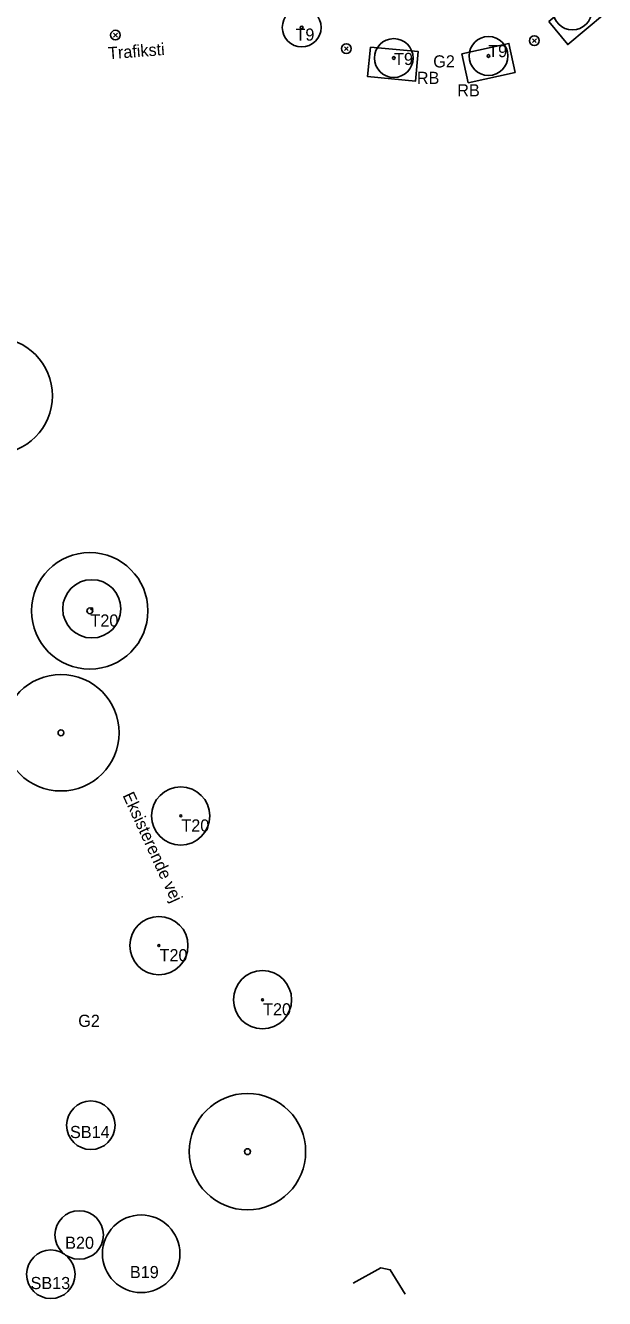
# Model space of a CAD drawing. Extents: x 0 to 512122, y 0 to 6212554.
# Drawn here: x 511804.4 to 511864.2, y 6211694 to 6211825.1 of the extents above; entities that cross this region are included whole.
import ezdxf

# ---------------------------------------------------------------- set-up
doc = ezdxf.new("R2010")
doc.units = 0
for name, color, linetype in [('_eks bevares træer', 7, 'Continuous'), ('_Fjernes træer', 7, 'Continuous'), ('_lights', 7, 'Continuous'), ('_ny træer T20', 7, 'Continuous'), ('_Rodvenligtbærelag', 7, 'Continuous'), ('L40 jord udlagt muld og grøft', 7, 'Continuous'), ('Skel', 7, 'Continuous'), ('TV_U_AFM_Symbl_Gul', 7, 'Continuous'), ('TV_U_LYS_Mastenummer', 7, 'Continuous')]:
    doc.layers.add(name, color=color, linetype=linetype)

# ---------------------------------------------------------------- blocks, each defined once
blk = doc.blocks.new('SOLITAIRE TREES')
at = {"layer": 'Skel'}
for radius in [2, 0.141]:
    blk.add_circle((0, 0), radius, dxfattribs=at)

msp = doc.modelspace()

# ---------------------------------------------------------------- linework, layer by layer
at = {"layer": '_eks bevares træer'}
for centre, radius in [((511808.08, 6211752.27), 6), ((511808.08, 6211752.27), 6), ((511808.08, 6211752.27), 0.3), ((511827.32, 6211709.11), 6), ((511827.32, 6211709.11), 6), ((511827.32, 6211709.11), 0.3)]:
    msp.add_circle(centre, radius, dxfattribs=at)
at = {"layer": '_Fjernes træer'}
for centre, radius in [((511801.2, 6211786.99), 6), ((511811.05, 6211764.83), 6), ((511811.05, 6211764.83), 0.3)]:
    msp.add_circle(centre, radius, dxfattribs=at)
at = {"layer": '_lights'}
for p, q in [((511813.9, 6211824.35), (511813.51, 6211823.95)), ((511813.51, 6211824.34), (511813.9, 6211823.95)), ((511837.32, 6211822.95), (511837.72, 6211822.56)), ((511837.72, 6211822.96), (511837.33, 6211822.56)), ((511857.12, 6211823.78), (511856.72, 6211823.39)), ((511856.72, 6211823.78), (511857.11, 6211823.38))]:
    msp.add_line(p, q, dxfattribs=at)
for centre, start, end in [((511813.7, 6211824.15), 315.5636, 315), ((511813.7, 6211824.15), 315, 315.5636), ((511837.52, 6211822.76), 315.5636, 315), ((511856.91, 6211823.58), 315.5636, 315), ((511856.91, 6211823.58), 315, 315.5636), ((511837.52, 6211822.76), 315, 315.5636)]:
    msp.add_arc(centre, 0.5, start, end, dxfattribs=at)
at = {"layer": '_ny træer T20'}
for centre, radius in [((511811.26, 6211765.04), 3), ((511811.26, 6211765.04), 3), ((511811.26, 6211765.04), 0.1), ((511820.43, 6211743.7), 3), ((511820.43, 6211743.7), 3), ((511820.43, 6211743.7), 0.1), ((511818.18, 6211730.34), 3), ((511818.18, 6211730.34), 3), ((511818.18, 6211730.34), 0.1), ((511828.87, 6211724.76), 3), ((511828.87, 6211724.76), 3), ((511828.87, 6211724.76), 0.1)]:
    msp.add_circle(centre, radius, dxfattribs=at)
at = {"layer": '_Rodvenligtbærelag'}
for points in [[(511858.39, 6211825.54), (511862.2, 6211828.71), (511864.16, 6211826.35), (511860.35, 6211823.18)], [(511840, 6211822.92), (511844.93, 6211822.45), (511844.64, 6211819.4), (511839.71, 6211819.88)], [(511849.44, 6211822.23), (511854.28, 6211823.29), (511854.93, 6211820.3), (511850.09, 6211819.24)]]:
    msp.add_lwpolyline(points, close=True, dxfattribs=at)
at = {"layer": 'L40 jord udlagt muld og grøft'}
msp.add_lwpolyline([(511838.21, 6211695.57), (511841.07, 6211697.15), (511842.04, 6211696.95), (511843.58, 6211694.44)], dxfattribs=at)
at = {"layer": 'TV_U_LYS_Mastenummer'}
for centre, radius in [((511811.16, 6211711.83), 2.5), ((511811.16, 6211711.83), 2.5), ((511809.96, 6211700.53), 2.5), ((511809.96, 6211700.53), 2.5), ((511816.35, 6211698.59), 4), ((511816.35, 6211698.59), 4), ((511807.03, 6211696.48), 2.5), ((511807.03, 6211696.48), 2.5)]:
    msp.add_circle(centre, radius, dxfattribs=at)

# ---------------------------------------------------------------- block references
at = {"layer": 'Skel'}
for p in [(511860.84, 6211826.68), (511832.91, 6211824.94), (511842.41, 6211821.79), (511852.18, 6211822)]:
    msp.add_blockref('SOLITAIRE TREES', p, dxfattribs=at)

# ---------------------------------------------------------------- texts
at = {"layer": 'TV_U_AFM_Symbl_Gul'}
for s, p in [('T9', (511832.27, 6211823.58)), ('T9', (511852.15, 6211821.88)), ('T9', (511842.44, 6211821.07)), ('G2', (511846.48, 6211820.82)), ('RB', (511844.79, 6211819.12)), ('RB', (511848.96, 6211817.84)), ('T20', (511811.12, 6211763.21)), ('T20', (511820.5, 6211742.09)), ('T20', (511818.25, 6211728.73)), ('G2', (511809.86, 6211721.97)), ('T20', (511828.93, 6211723.15)), ('SB14', (511809.01, 6211710.51)), ('B20', (511808.51, 6211699.1)), ('B19', (511815.19, 6211696.08)), ('SB13', (511804.94, 6211694.95))]:
    msp.add_text(s, height=1.25, dxfattribs=at).set_placement(p)
for s, rotation, p in [('Trafiksti', 4.3308, (511812.98, 6211821.66)), ('Eksisterende vej', 294.6577, (511814.41, 6211745.82))]:
    msp.add_text(s, height=1.25, rotation=rotation, dxfattribs=at).set_placement(p)

doc.saveas('drawing.dxf')
